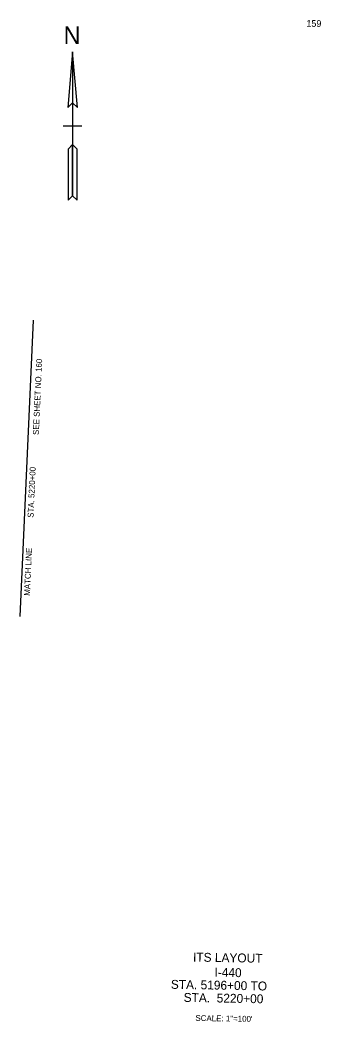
# Model space of a CAD drawing. Extents: x -200 to 1737414, y -325 to 650780.
# Drawn here: x 1736806 to 1737414, y 648753 to 650780 of the extents above; entities that cross this region are included whole.
import ezdxf

# ---------------------------------------------------------------- set-up
doc = ezdxf.new("R2010")
doc.units = 0
for name, color, linetype in [('DESIGN - CENTERLINE - Proposed Text', 7, 'Continuous'), ('DESIGN - SCRATCH - User 1', 7, 'Continuous'), ('DESIGN - SHEET - Corner Text', 7, 'Continuous'), ('ITS - CONST TEXT', 7, 'Continuous'), ('ITS - EXISITING WEATHER STATION', 7, 'Continuous'), ('ITS - EXISTING COMM CABLE', 7, 'Continuous'), ('ITS - EXISTING HAR', 7, 'Continuous')]:
    doc.layers.add(name, color=color, linetype=linetype)

msp = doc.modelspace()

# ---------------------------------------------------------------- linework, layer by layer
at = {"layer": 'DESIGN - CENTERLINE - Proposed Text'}
for p, q in [((1736911.7, 650565.4), (1736892.8, 650565.4)), ((1736930.6, 650565.4), (1736911.7, 650565.4))]:
    msp.add_line(p, q, dxfattribs=at)
msp.add_lwpolyline([(1736911.7, 650715.4), (1736901.9, 650602.8), (1736911.7, 650612.6), (1736921.5, 650602.8), (1736911.7, 650715.4), (1736911.7, 650424.5), (1736920.8, 650415.4), (1736920.8, 650518.9), (1736911.7, 650528), (1736902.6, 650518.9), (1736902.6, 650415.4), (1736911.7, 650424.5)], dxfattribs=at)
for points in [[(1736911.7, 650612.6), (1736921.5, 650602.8), (1736911.7, 650715.4)], [(1736902.6, 650415.4), (1736911.7, 650424.5), (1736911.7, 650528), (1736902.6, 650518.9)]]:
    msp.add_lwpolyline(points, close=True, dxfattribs=at)
at = {"layer": 'DESIGN - SCRATCH - User 1'}
for p, q in [((1737241.3, 648839.4), (1737241.3, 648839.4)), ((1737241.3, 648839.4), (1737241.3, 648839.4)), ((1737244.3, 648822.9), (1737244.3, 648822.9))]:
    msp.add_line(p, q, dxfattribs=at)
at = {"layer": 'ITS - EXISITING WEATHER STATION'}
msp.add_line((1737241.2, 648839.5), (1737241.2, 648839.5), dxfattribs=at)
msp.add_line((1737241.2, 648839.5), (1737241.2, 648839.5), dxfattribs=at)
at = {"layer": 'ITS - EXISTING COMM CABLE'}
msp.add_line((1736805.5, 649573), (1736832.7, 650172.4), dxfattribs=at)

# ---------------------------------------------------------------- texts
at = {"layer": 'DESIGN - CENTERLINE - Proposed Text'}
msp.add_text('N', height=35.4, dxfattribs=at).set_placement((1736893.6, 650731.5))
at = {"layer": 'DESIGN - SHEET - Corner Text'}
msp.add_text('159', height=13.5, rotation=358.9359, dxfattribs=at).set_placement((1737384.7, 650766.5))
at = {"layer": 'ITS - CONST TEXT'}
msp.add_text('SCALE: 1"=100\'', height=12, rotation=358.936, dxfattribs=at).set_placement((1737160.2, 648754.9))
at = {"layer": 'ITS - EXISTING COMM CABLE'}
for s, p in [('SEE SHEET NO. 160 ', (1736843.4, 649940.2)), ('STA. 5220+00', (1736832.6, 649772.6)), ('MATCH LINE', (1736825.4, 649614.8))]:
    msp.add_text(s, height=12, rotation=87.4013, dxfattribs=at).set_placement(p)
at = {"layer": 'ITS - EXISTING HAR'}
for s, p in [('ITS LAYOUT', (1737155.3, 648875)), ('I-440', (1737198.7, 648844.3)), ('STA. 5196+00 TO', (1737110.4, 648819.9)), ('STA.  5220+00', (1737136.3, 648793.4))]:
    msp.add_text(s, height=18, rotation=358.936, dxfattribs=at).set_placement(p)

doc.saveas('drawing.dxf')
